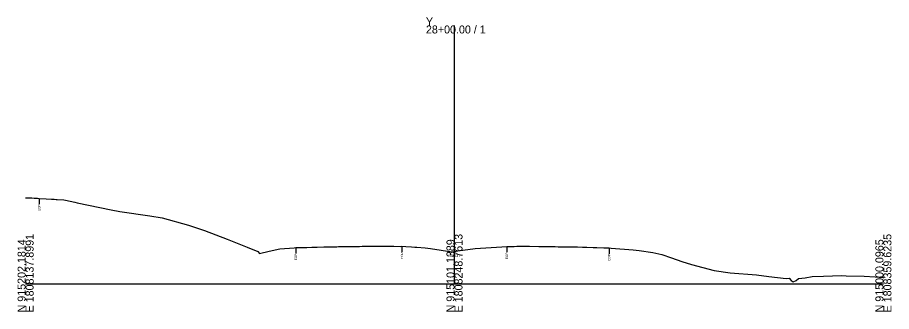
# Model space of a CAD drawing. Extents: x -26 to 3303, y -30 to 9580.
# Drawn here: x 997.2 to 1302.8, y 7990.3 to 8093.3 of the extents above; entities that cross this region are included whole.
import ezdxf

# ---------------------------------------------------------------- set-up
doc = ezdxf.new("R2010")
doc.units = 0
for name, color, linetype in [('Exist Cross Section Cell', 7, 'Continuous'), ('Exist XS Center Line Elevation Label', 7, 'Continuous'), ('Exist XS Ground Line', 7, 'Continuous'), ('Old_Level_10', 7, 'Continuous')]:
    doc.layers.add(name, color=color, linetype=linetype)

msp = doc.modelspace()

# ---------------------------------------------------------------- linework, layer by layer
at = {"layer": 'Exist Cross Section Cell'}
for p, q in [((1150, 8000), (1150, 8090.47)), ((1000, 8000), (1150, 8000)), ((1150, 8000), (1300, 8000))]:
    msp.add_line(p, q, dxfattribs=at)
at = {"layer": 'Exist XS Ground Line'}
msp.add_lwpolyline([(1000, 8030.15), (1001.36, 8030.16), (1002.14, 8030.09), (1002.96, 8030.01), (1004.16, 8029.96), (1004.75, 8029.94), (1007.24, 8029.78), (1009.05, 8029.67), (1010.03, 8029.61), (1010.65, 8029.57), (1011.07, 8029.54), (1013.32, 8029.39), (1013.92, 8029.27), (1017.19, 8028.56), (1018.08, 8028.34), (1029.9, 8025.89), (1032.93, 8025.34), (1043.43, 8023.85), (1047.77, 8023.12), (1056.96, 8020.55), (1062.62, 8018.63), (1070.49, 8015.61), (1077.46, 8012.85), (1081.24, 8011.3), (1081.8, 8010.63), (1085.19, 8011.41), (1088.93, 8012.25), (1093.93, 8012.64), (1094.5, 8012.68), (1095.29, 8012.7), (1096.52, 8012.73), (1098.32, 8012.77), (1100.06, 8012.79), (1101.65, 8012.81), (1102, 8012.82), (1104.32, 8012.95), (1105.22, 8012.96), (1105.73, 8012.97), (1107.12, 8012.99), (1108.41, 8013.01), (1108.9, 8013.02), (1109.43, 8013.03), (1110.66, 8013.04), (1111.79, 8013.05), (1113.16, 8013.07), (1114.2, 8013.08), (1115.8, 8013.11), (1116.83, 8013.13), (1117.75, 8013.14), (1118.57, 8013.15), (1120.59, 8013.17), (1121.3, 8013.18), (1121.95, 8013.18), (1123.05, 8013.18), (1124.25, 8013.19), (1124.83, 8013.19), (1125.34, 8013.2), (1127.3, 8013.21), (1127.72, 8013.22), (1128.27, 8013.18), (1128.74, 8013.16), (1131.01, 8013.13), (1131.63, 8013.15), (1132.96, 8013.06), (1134.99, 8012.91), (1136.09, 8012.86), (1136.79, 8012.82), (1139.71, 8012.64), (1141.66, 8012.34), (1149.08, 8011.25), (1150, 8011.37), (1151.19, 8011.54), (1157.22, 8012.4), (1166.52, 8012.99), (1168.31, 8013.09), (1169.33, 8013.1), (1170.83, 8013.1), (1171.8, 8013.18), (1172.44, 8013.22), (1174.58, 8013.19), (1176.21, 8013.17), (1179.49, 8013.13), (1179.94, 8013.13), (1181.45, 8013.1), (1182.85, 8013.08), (1183.69, 8013.06), (1184.15, 8013.06), (1185.19, 8013.03), (1186.21, 8013.01), (1186.76, 8013), (1187.36, 8012.99), (1188.53, 8012.98), (1189.59, 8012.97), (1191.05, 8012.95), (1192.96, 8012.92), (1194.75, 8012.89), (1195.19, 8012.88), (1195.91, 8012.86), (1196.33, 8012.82), (1198.55, 8012.71), (1199.79, 8012.69), (1202.17, 8012.65), (1203.3, 8012.62), (1204.05, 8012.59), (1204.84, 8012.53), (1212.44, 8011.94), (1214.58, 8011.71), (1219.33, 8010.94), (1222.47, 8010.28), (1225.92, 8009.13), (1229.55, 8007.84), (1232.86, 8006.75), (1240.76, 8004.67), (1246.39, 8003.88), (1255.61, 8003.11), (1259.92, 8002.58), (1265.95, 8001.93), (1267.08, 8002.03), (1267.79, 8001.22), (1268.45, 8000.75), (1269.52, 8001.22), (1270.36, 8001.87), (1272.66, 8002.16), (1275.12, 8002.52), (1279.1, 8002.74), (1285.3, 8002.88), (1286.98, 8002.86), (1293.26, 8002.66), (1297.12, 8002.47), (1299.84, 8002.26), (1300, 8002.08)], dxfattribs=at)
at = {"layer": 'Old_Level_10'}
for p, q in [((1004.75, 8029.94), (1004.75, 8027.89)), ((1094.5, 8012.68), (1094.5, 8010.63)), ((1131.63, 8013.15), (1131.63, 8011.1)), ((1168.31, 8013.09), (1168.31, 8011.04)), ((1204.05, 8012.59), (1204.05, 8010.54))]:
    msp.add_line(p, q, dxfattribs=at)

# ---------------------------------------------------------------- texts
at = {"layer": 'Exist Cross Section Cell'}
for s, p in [('Y', (1140, 8090.47)), ('28+00.00 / 1', (1140, 8087.67))]:
    msp.add_text(s, height=2.8, dxfattribs=at).set_placement(p)
for s, p in [('N 915202.1814', (1000, 7990)), ('E 1808137.8991', (1002.8, 7990)), ('N 915101.1389', (1150, 7990)), ('E 1808248.7613', (1152.8, 7990)), ('N 915000.0965', (1300, 7990)), ('E 1808359.6235', (1302.8, 7990))]:
    msp.add_text(s, height=2.8, rotation=90, dxfattribs=at).set_placement(p)
at = {"layer": 'Exist XS Center Line Elevation Label'}
msp.add_text('667.37', height=1, dxfattribs=at).set_placement((1147.85, 8009.37))
at = {"layer": 'Old_Level_10'}
for p in [(1005.15, 8025.49), (1094.9, 8008.23), (1132.02, 8008.7), (1168.7, 8008.64), (1204.45, 8008.14)]:
    msp.add_text('EOP', height=0.787, rotation=90, dxfattribs=at).set_placement(p)

doc.saveas('drawing.dxf')
